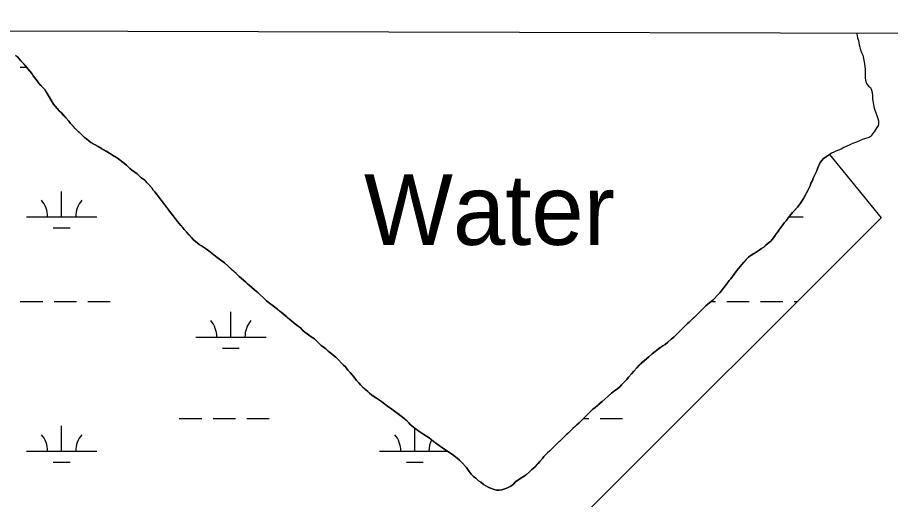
# Model space of a CAD drawing. Extents: x 3177185 to 3215018, y 812988 to 838321.
# Drawn here: x 3189655 to 3190895, y 835902 to 836586 of the extents above; entities that cross this region are included whole.
import ezdxf

# ---------------------------------------------------------------- set-up
doc = ezdxf.new("R2010")
doc.units = 0
for name, color, linetype in [('V-GRID-FRAM', 7, 'Continuous'), ('V-RIVR-IDEN', 7, 'Continuous'), ('V-TOPO-SHOR', 7, 'Continuous'), ('V-WETL-SWMP', 7, 'Continuous')]:
    doc.layers.add(name, color=color, linetype=linetype)

msp = doc.modelspace()

# ---------------------------------------------------------------- linework, layer by layer
at = {"layer": 'V-GRID-FRAM'}
msp.add_lwpolyline([(3181402.4, 836586.1), (3212801.6, 836513), (3212767.2, 818326.1), (3181352.2, 818399.3), (3181402.4, 836586.1)], dxfattribs=at)
at = {"layer": 'V-TOPO-SHOR'}
for points in [[(3190847.1, 836564.1), (3190847.1, 836564.1), (3190847.9, 836560.3), (3190848.6, 836556.5), (3190849.6, 836553.3), (3190850.9, 836547.4), (3190851.9, 836543.7), (3190852.7, 836539.9), (3190854.2, 836536.4), (3190855.8, 836532.6), (3190856.8, 836527.8), (3190857.8, 836523.3), (3190858.8, 836516.3), (3190859.3, 836512), (3190859.4, 836503.2), (3190859.1, 836499.7), (3190860.1, 836495.1), (3190861.2, 836492.2), (3190864.1, 836488.7), (3190866.7, 836486.5), (3190868.5, 836483), (3190869.3, 836479.5), (3190869.5, 836475), (3190869.7, 836469.9), (3190870.5, 836465.3), (3190871.5, 836459.2), (3190872.5, 836455.7), (3190874.6, 836450.6), (3190875.8, 836446.8), (3190877.4, 836442.8), (3190878.2, 836439.3), (3190878.4, 836435.5), (3190877.8, 836432.3), (3190875.9, 836429.7), (3190872.1, 836423.8), (3190869.9, 836420.7), (3190867.7, 836417.7), (3190865, 836415.9), (3190861.5, 836414.9), (3190856.4, 836413.1), (3190852.1, 836411.2), (3190847, 836409.2), (3190844.1, 836407.9), (3190839.5, 836406.1), (3190836.3, 836405), (3190829, 836401.4), (3190825.2, 836399.3), (3190821.2, 836397.7), (3190817.7, 836396.2), (3190814.7, 836394.9), (3190811.2, 836393.6), (3190808, 836391.2), (3190804.5, 836388.6), (3190799.6, 836385.2), (3190797.5, 836383.1), (3190795.3, 836380.1), (3190792.2, 836372.7), (3190790, 836367.6), (3190788.4, 836363.4), (3190785.6, 836357.8), (3190784.3, 836354.6)], [(3189695.3, 836480.3), (3189693.5, 836483.8), (3189690.3, 836487.3), (3189687.9, 836489.7), (3189684.5, 836493.5), (3189682.7, 836495.9), (3189680.8, 836498.6), (3189677.1, 836503.2), (3189675, 836506.5), (3189672.1, 836510), (3189669.2, 836513.8), (3189666.3, 836517.6), (3189664.2, 836519.7), (3189659.7, 836524.3), (3189657.4, 836527), (3189654.7, 836530)], [(3190060.4, 836141.8), (3190056.7, 836145.3), (3190054.3, 836147.2), (3190051.9, 836149.1), (3190047.7, 836152.1), (3190044, 836155.4), (3190041.3, 836157.6), (3190036.8, 836161.4), (3190034.5, 836163.3), (3190029.4, 836167.6), (3190026.8, 836169.8), (3190024.1, 836172), (3190018, 836176.6), (3190012.7, 836180.7), (3190008.8, 836183.9), (3190004.3, 836188), (3189999.3, 836192.9), (3189996.1, 836195.6), (3189991.6, 836199.6), (3189984.2, 836206.2), (3189981.5, 836208.1), (3189979.4, 836210.2), (3189976, 836213.2), (3189969.9, 836218.1), (3189965.4, 836222.5), (3189962.2, 836225.4), (3189959, 836228.4), (3189953.5, 836233.6), (3189948.7, 836237.6), (3189945, 836240.6), (3189938.7, 836245.5), (3189936, 836247.2), (3189932.3, 836250.2), (3189926.5, 836254.8), (3189921.7, 836258), (3189916.4, 836261.9), (3189913, 836264), (3189907.9, 836267.9), (3189905, 836270.6), (3189901.8, 836273.8), (3189898.4, 836277.6), (3189894.7, 836281.7), (3189891.8, 836284.9), (3189889.2, 836288.2), (3189887.1, 836290.6), (3189884.7, 836293.6), (3189882.3, 836296.3), (3189879.2, 836300.3), (3189874.2, 836306.8), (3189871, 836311.1), (3189865.8, 836317.9), (3189862.1, 836322.5), (3189858.9, 836326.5), (3189856, 836330.6), (3189853.1, 836334.4), (3189849.7, 836338.7), (3189847.6, 836341.1), (3189845.5, 836344.1), (3189839.2, 836351.1), (3189835.7, 836354.9), (3189833.1, 836356.8), (3189830.2, 836359), (3189827.8, 836361.2), (3189824.9, 836364.1), (3189821.7, 836366.6), (3189816.9, 836369.6), (3189814.6, 836371.5), (3189812.2, 836373.9), (3189809.5, 836376.6), (3189806.9, 836378.8), (3189801.3, 836382.9), (3189798.7, 836384.8), (3189795.5, 836387.2), (3189789.7, 836390.8), (3189785.7, 836393.5), (3189780.6, 836396.3), (3189774.3, 836400.1), (3189769.2, 836403.1), (3189765, 836405.3), (3189759.1, 836408.6), (3189756.5, 836410.7), (3189752.8, 836413.7), (3189749.8, 836415.9), (3189745.1, 836420.3), (3189740.9, 836424.3), (3189736.6, 836428.4), (3189734.3, 836431.1), (3189730.3, 836435.7), (3189727.9, 836438.9), (3189724, 836443), (3189720.8, 836446.5), (3189717.1, 836450.6), (3189714.2, 836453.5), (3189711.8, 836456.5), (3189708.1, 836460.3), (3189705.8, 836463), (3189695.3, 836480.3)], [(3190784.3, 836354.6), (3190782.1, 836350.9), (3190780.9, 836346.9), (3190779, 836343.2), (3190777.7, 836340.2), (3190775.5, 836336.3), (3190771.6, 836329.1), (3190767.5, 836322.4), (3190765.6, 836320.1), (3190763.2, 836316.9), (3190759.1, 836312.4), (3190755.9, 836309), (3190754, 836306.6), (3190751.8, 836303.9), (3190749.6, 836301), (3190746.9, 836297.6), (3190744.2, 836294.4), (3190742.5, 836291.7), (3190739.5, 836288), (3190737.6, 836285.4), (3190735.2, 836281.9), (3190732.7, 836279), (3190730.6, 836275.3), (3190727.3, 836270.8), (3190725.1, 836268.7), (3190721.6, 836265.5), (3190717.6, 836262.4), (3190715.4, 836260), (3190712.1, 836258.2), (3190708.6, 836255.8), (3190703, 836252.1), (3190700.3, 836250.5), (3190696, 836247.9), (3190693.3, 836245.8), (3190690.3, 836242.7), (3190686.8, 836238.9), (3190683.8, 836235.2), (3190681.6, 836232.3), (3190677, 836226.8), (3190672.9, 836221.5), (3190668.5, 836215.1), (3190666.1, 836212.5), (3190661.2, 836205.8), (3190659, 836203.2), (3190652.8, 836195.2), (3190649.2, 836191.5), (3190645.4, 836187.3), (3190642.7, 836184.9), (3190636, 836179.7), (3190632.7, 836176.8), (3190629.8, 836173.9), (3190624.3, 836168.3), (3190621.9, 836165.9), (3190619.5, 836163.3), (3190614, 836158), (3190609.4, 836153.5), (3190607, 836151.7), (3190603.5, 836148.3), (3190598.9, 836143.8), (3190595.1, 836139.8), (3190592.9, 836137.7), (3190590.7, 836135.3), (3190587.5, 836132.4), (3190583.7, 836129.5), (3190579.1, 836125), (3190575.1, 836121.9), (3190571.6, 836120), (3190568.9, 836117.9), (3190565.6, 836115.6), (3190560.8, 836111.9), (3190556.4, 836108.7), (3190551.8, 836104.2), (3190545.6, 836099), (3190541.6, 836095.6), (3190538.3, 836092.6), (3190535, 836088.7), (3190530.4, 836083.9), (3190527.2, 836080), (3190522.8, 836075.5), (3190520.4, 836072.3), (3190516.3, 836067.8), (3190513.1, 836064.3), (3190510.9, 836061.7), (3190507.9, 836059.3), (3190503.1, 836055.9), (3190499, 836052.5), (3190493.9, 836048.5), (3190485.5, 836040.9), (3190481.4, 836037.5), (3190479, 836035.4), (3190475.8, 836032.5), (3190472.5, 836030.1), (3190468.2, 836025.9), (3190465.5, 836023.2), (3190462.2, 836020.1), (3190459.5, 836017.1), (3190456, 836013.7), (3190453, 836010.8), (3190449.8, 836007.9), (3190447.3, 836005.5), (3190444.1, 836002.4)], [(3190444.1, 836002.4), (3190441.1, 835999.7), (3190437.8, 835996.6), (3190435.4, 835994.5), (3190431.4, 835990.8), (3190427.6, 835987.1), (3190423.5, 835983.1), (3190420, 835979.7), (3190416.5, 835976.2), (3190414.3, 835974.1), (3190410.5, 835970.4), (3190408.1, 835968.1), (3190402.9, 835963), (3190400.7, 835960.1), (3190397.2, 835955.9), (3190394.5, 835953), (3190390.2, 835948.2), (3190385.6, 835944.3), (3190382.3, 835940.8), (3190377.4, 835936.6), (3190374.7, 835934.8), (3190369.9, 835932.2), (3190365.6, 835929), (3190362.6, 835926.9), (3190359.6, 835923.7), (3190355.8, 835920.8), (3190352.1, 835918.7), (3190348.8, 835917.2), (3190343.2, 835915.4), (3190339.2, 835914.9), (3190335.4, 835914.9), (3190332.2, 835915.8), (3190326.9, 835918), (3190323.7, 835919.1), (3190320.3, 835921), (3190316.8, 835923.2), (3190313.1, 835926.2), (3190309.9, 835928.1), (3190306.2, 835931.9), (3190302.5, 835934.6), (3190299.3, 835937.9), (3190296.7, 835941.4), (3190292.8, 835947), (3190285.9, 835954.9), (3190283, 835957.6), (3190279.6, 835960.6), (3190275.1, 835963.6), (3190271.6, 835966.6), (3190267.4, 835969.3), (3190263.4, 835971.8), (3190254.4, 835978), (3190250.4, 835980.8), (3190247.8, 835982.9), (3190243.5, 835986.2), (3190239.8, 835989.2), (3190232.1, 835993.8), (3190226.3, 835997.9), (3190223.6, 835999.8), (3190219.9, 836002.5), (3190212.8, 836008.3), (3190210.7, 836010.7), (3190208.3, 836012.9), (3190204.6, 836016.1), (3190201.9, 836018.8), (3190195.3, 836023.7), (3190192.4, 836025.9), (3190186.6, 836030), (3190180.7, 836034.3), (3190174.4, 836039.2), (3190172, 836041.1), (3190169.3, 836043), (3190165.1, 836045.5), (3190158.5, 836050.1), (3190154.8, 836052.9), (3190152.6, 836055), (3190147.6, 836059.4), (3190145.2, 836061.5), (3190142.3, 836064.5), (3190140, 836067.2), (3190136.3, 836070.7), (3190132.6, 836076.1), (3190130.5, 836078.6), (3190127.6, 836082.1), (3190124.4, 836085.3), (3190120.7, 836089.9), (3190118.1, 836092.6), (3190115.2, 836095.4), (3190111, 836100), (3190107.3, 836103.8), (3190103.5, 836106.7), (3190100.1, 836109.7), (3190096.4, 836112.5), (3190092.7, 836115.7), (3190089.3, 836118.4), (3190086.3, 836120.6), (3190079.2, 836127.4), (3190076.6, 836129.8), (3190072, 836132.8), (3190066.5, 836136.9), (3190063.3, 836139.4), (3190060.4, 836141.8)]]:
    msp.add_lwpolyline(points, dxfattribs=at)
at = {"layer": 'V-WETL-SWMP'}
for p, q in [((3189652.1, 836532.4), (3189654.7, 836530)), ((3189654.7, 836530), (3189659.7, 836524.3)), ((3189658.7, 836515.6), (3189667.8, 836515.6)), ((3189659.7, 836524.3), (3189666.3, 836517.6)), ((3189666.3, 836517.6), (3189672.1, 836510)), ((3189672.1, 836510), (3189675, 836506.5)), ((3189675, 836506.5), (3189677.1, 836503.2)), ((3189677.1, 836503.2), (3189680.8, 836498.6)), ((3189680.8, 836498.6), (3189682.7, 836495.9)), ((3189682.7, 836495.9), (3189684.5, 836493.5)), ((3189684.5, 836493.5), (3189693.5, 836483.8)), ((3189693.5, 836483.8), (3189695.3, 836480.3)), ((3189695.3, 836480.3), (3189705.8, 836463)), ((3189705.8, 836463), (3189708.1, 836460.3)), ((3189708.1, 836460.3), (3189711.8, 836456.5)), ((3189711.8, 836456.5), (3189714.2, 836453.5)), ((3189714.2, 836453.5), (3189717.1, 836450.6)), ((3189717.1, 836450.6), (3189724, 836443)), ((3189724, 836443), (3189727.9, 836438.9)), ((3189727.9, 836438.9), (3189730.3, 836435.7)), ((3189730.3, 836435.7), (3189736.6, 836428.4)), ((3189736.6, 836428.4), (3189745.1, 836420.3)), ((3189745.1, 836420.3), (3189749.8, 836415.9)), ((3189749.8, 836415.9), (3189752.8, 836413.7)), ((3189752.8, 836413.7), (3189759.1, 836408.6)), ((3189759.1, 836408.6), (3189765, 836405.3)), ((3189765, 836405.3), (3189769.2, 836403.1)), ((3189769.2, 836403.1), (3189780.6, 836396.3)), ((3189780.6, 836396.3), (3189785.7, 836393.5)), ((3189785.7, 836393.5), (3189789.7, 836390.8)), ((3189789.7, 836390.8), (3189795.5, 836387.2)), ((3190799.6, 836385.2), (3190804.5, 836388.6)), ((3190804.5, 836388.6), (3190808.5, 836391.6)), ((3190808.5, 836391.6), (3190882, 836301.5)), ((3189795.5, 836387.2), (3189798.7, 836384.8)), ((3189798.7, 836384.8), (3189806.9, 836378.8)), ((3189806.9, 836378.8), (3189809.5, 836376.6)), ((3189809.5, 836376.6), (3189814.6, 836371.5)), ((3190792.2, 836372.7), (3190795.3, 836380.1)), ((3190795.3, 836380.1), (3190797.5, 836383.1)), ((3190797.5, 836383.1), (3190799.6, 836385.2)), ((3189814.6, 836371.5), (3189816.9, 836369.6)), ((3189816.9, 836369.6), (3189821.7, 836366.6)), ((3189821.7, 836366.6), (3189824.9, 836364.1)), ((3189824.9, 836364.1), (3189827.8, 836361.2)), ((3190788.4, 836363.4), (3190790, 836367.6)), ((3190790, 836367.6), (3190792.2, 836372.7)), ((3189827.8, 836361.2), (3189830.2, 836359)), ((3189830.2, 836359), (3189835.7, 836354.9)), ((3189835.7, 836354.9), (3189845.5, 836344.1)), ((3190782.1, 836350.9), (3190784.3, 836354.6)), ((3190784.3, 836354.6), (3190785.6, 836357.8)), ((3190785.6, 836357.8), (3190788.4, 836363.4)), ((3189717.5, 836303), (3189717.5, 836339)), ((3189845.5, 836344.1), (3189847.6, 836341.1)), ((3189847.6, 836341.1), (3189849.7, 836338.7)), ((3190771.6, 836329.1), (3190777.7, 836340.2)), ((3190777.7, 836340.2), (3190779, 836343.2)), ((3190779, 836343.2), (3190780.9, 836346.9)), ((3190780.9, 836346.9), (3190782.1, 836350.9)), ((3189849.7, 836338.7), (3189853.1, 836334.4)), ((3189853.1, 836334.4), (3189856, 836330.6)), ((3189856, 836330.6), (3189858.9, 836326.5)), ((3189858.9, 836326.5), (3189871, 836311.1)), ((3190767.5, 836322.4), (3190771.6, 836329.1)), ((3190755.9, 836309), (3190763.2, 836316.9)), ((3190763.2, 836316.9), (3190767.5, 836322.4)), ((3189667.5, 836303), (3189767.5, 836303)), ((3189871, 836311.1), (3189874.2, 836306.8)), ((3189874.2, 836306.8), (3189882.3, 836296.3)), ((3190882, 836301.5), (3190197.3, 835618.5)), ((3190746.9, 836297.6), (3190751.8, 836303.9)), ((3190751.1, 836303), (3190771.3, 836303)), ((3190751.8, 836303.9), (3190755.9, 836309)), ((3189882.3, 836296.3), (3189884.7, 836293.6)), ((3189884.7, 836293.6), (3189891.8, 836284.9)), ((3190739.5, 836288), (3190742.5, 836291.7)), ((3190742.5, 836291.7), (3190744.2, 836294.4)), ((3190744.2, 836294.4), (3190746.9, 836297.6)), ((3189705.5, 836287.6), (3189729.5, 836287.6)), ((3189891.8, 836284.9), (3189894.7, 836281.7)), ((3189894.7, 836281.7), (3189901.8, 836273.8)), ((3190730.6, 836275.3), (3190732.7, 836279)), ((3190732.7, 836279), (3190735.2, 836281.9)), ((3190735.2, 836281.9), (3190739.5, 836288)), ((3189901.8, 836273.8), (3189905, 836270.6)), ((3189905, 836270.6), (3189907.9, 836267.9)), ((3189907.9, 836267.9), (3189913, 836264)), ((3190717.5, 836262.4), (3190721.6, 836265.5)), ((3190721.6, 836265.5), (3190725.1, 836268.7)), ((3190725.1, 836268.7), (3190727.3, 836270.8)), ((3190727.3, 836270.8), (3190730.6, 836275.3)), ((3189913, 836264), (3189916.4, 836261.9)), ((3189916.4, 836261.9), (3189921.7, 836258)), ((3189921.7, 836258), (3189926.5, 836254.8)), ((3189926.5, 836254.8), (3189936, 836247.2)), ((3190696, 836247.9), (3190703, 836252.1)), ((3190703, 836252.1), (3190712.1, 836258.2)), ((3190712.1, 836258.2), (3190715.4, 836260)), ((3190715.4, 836260), (3190717.5, 836262.4)), ((3189936, 836247.2), (3189938.7, 836245.5)), ((3189938.7, 836245.5), (3189945, 836240.6)), ((3189945, 836240.6), (3189948.7, 836237.6)), ((3190686.8, 836238.9), (3190693.3, 836245.8)), ((3190693.3, 836245.8), (3190696, 836247.9)), ((3189948.7, 836237.6), (3189953.5, 836233.6)), ((3189953.5, 836233.6), (3189965.4, 836222.5)), ((3190677, 836226.8), (3190681.6, 836232.3)), ((3190681.6, 836232.3), (3190683.8, 836235.2)), ((3190683.8, 836235.2), (3190686.8, 836238.9)), ((3189965.4, 836222.5), (3189969.9, 836218.1)), ((3189969.9, 836218.1), (3189976, 836213.2)), ((3190666.1, 836212.5), (3190668.5, 836215.1)), ((3190668.5, 836215.1), (3190672.9, 836221.5)), ((3190672.9, 836221.5), (3190677, 836226.8)), ((3189976, 836213.2), (3189979.4, 836210.2)), ((3189979.4, 836210.2), (3189981.5, 836208.1)), ((3189981.5, 836208.1), (3189984.2, 836206.2)), ((3189984.2, 836206.2), (3189991.6, 836199.6)), ((3190652.8, 836195.2), (3190661.2, 836205.8)), ((3190661.2, 836205.8), (3190666.1, 836212.5)), ((3189991.6, 836199.6), (3189996.1, 836195.6)), ((3189996.1, 836195.6), (3189999.3, 836192.9)), ((3189999.3, 836192.9), (3190004.3, 836188)), ((3190645.4, 836187.3), (3190649.2, 836191.5)), ((3190649.2, 836191.5), (3190652.8, 836195.2)), ((3189658.7, 836182.9), (3189690.7, 836182.9)), ((3189706.7, 836182.9), (3189738.7, 836182.9)), ((3189754.7, 836182.9), (3189786.7, 836182.9)), ((3190004.3, 836188), (3190008.8, 836183.9)), ((3190008.8, 836183.9), (3190012.7, 836180.7)), ((3190012.7, 836180.7), (3190024.1, 836172)), ((3190632.7, 836176.8), (3190636, 836179.7)), ((3190636, 836179.7), (3190642.7, 836184.9)), ((3190640.1, 836182.9), (3190646.5, 836182.9)), ((3190642.7, 836184.9), (3190645.4, 836187.3)), ((3190662.5, 836182.9), (3190694.5, 836182.9)), ((3190710.5, 836182.9), (3190742.5, 836182.9)), ((3190758.5, 836182.9), (3190763.1, 836182.9)), ((3189958, 836132.2), (3189958, 836168.2)), ((3190024.1, 836172), (3190044, 836155.4)), ((3190619.5, 836163.3), (3190621.9, 836165.9)), ((3190621.9, 836165.9), (3190632.7, 836176.8)), ((3190044, 836155.4), (3190047.7, 836152.1)), ((3190607, 836151.7), (3190609.4, 836153.5)), ((3190609.4, 836153.5), (3190619.5, 836163.3)), ((3190047.7, 836152.1), (3190051.9, 836149.1)), ((3190051.9, 836149.1), (3190056.7, 836145.3)), ((3190056.7, 836145.3), (3190060.4, 836141.8)), ((3190060.4, 836141.8), (3190063.3, 836139.4)), ((3190595.1, 836139.8), (3190598.9, 836143.8)), ((3190598.9, 836143.8), (3190607, 836151.7)), ((3189908, 836132.2), (3190008, 836132.2)), ((3190063.3, 836139.4), (3190072, 836132.8)), ((3190072, 836132.8), (3190076.6, 836129.8)), ((3190076.6, 836129.8), (3190086.3, 836120.6)), ((3190579.1, 836125), (3190583.7, 836129.5)), ((3190583.7, 836129.5), (3190587.5, 836132.4)), ((3190587.5, 836132.4), (3190590.7, 836135.3)), ((3190590.7, 836135.3), (3190592.9, 836137.7)), ((3190592.9, 836137.7), (3190595.1, 836139.8)), ((3189946, 836116.8), (3189970, 836116.8)), ((3190086.3, 836120.6), (3190092.7, 836115.7)), ((3190092.7, 836115.7), (3190096.4, 836112.4)), ((3190556.4, 836108.7), (3190568.9, 836117.9)), ((3190568.9, 836117.9), (3190571.6, 836120)), ((3190571.6, 836120), (3190575.1, 836121.9)), ((3190575.1, 836121.9), (3190579.1, 836125)), ((3190096.4, 836112.4), (3190100.1, 836109.7)), ((3190100.1, 836109.7), (3190103.5, 836106.7)), ((3190103.5, 836106.7), (3190107.3, 836103.8)), ((3190107.3, 836103.8), (3190111, 836100)), ((3190541.6, 836095.5), (3190551.8, 836104.2)), ((3190551.8, 836104.2), (3190556.4, 836108.7)), ((3190111, 836100), (3190115.2, 836095.4)), ((3190115.2, 836095.4), (3190118.1, 836092.6)), ((3190118.1, 836092.6), (3190120.7, 836089.9)), ((3190535, 836088.7), (3190538.3, 836092.6)), ((3190538.3, 836092.6), (3190541.6, 836095.5)), ((3190120.7, 836089.9), (3190124.4, 836085.3)), ((3190124.4, 836085.3), (3190127.6, 836082.1)), ((3190127.6, 836082.1), (3190132.6, 836076.1)), ((3190522.8, 836075.5), (3190527.2, 836080)), ((3190527.2, 836080), (3190530.4, 836083.9)), ((3190530.4, 836083.9), (3190535, 836088.7)), ((3190132.6, 836076.1), (3190136.3, 836070.7)), ((3190136.3, 836070.7), (3190140, 836067.2)), ((3190140, 836067.2), (3190142.3, 836064.5)), ((3190513.1, 836064.3), (3190520.4, 836072.3)), ((3190520.4, 836072.3), (3190522.8, 836075.5)), ((3190142.3, 836064.5), (3190145.2, 836061.5)), ((3190145.2, 836061.5), (3190152.6, 836055)), ((3190152.6, 836055), (3190154.8, 836052.9)), ((3190499, 836052.5), (3190503.1, 836055.9)), ((3190503.1, 836055.9), (3190507.9, 836059.3)), ((3190507.9, 836059.3), (3190510.9, 836061.7)), ((3190510.9, 836061.7), (3190513.1, 836064.3)), ((3190154.8, 836052.9), (3190158.5, 836050.1)), ((3190158.5, 836050.1), (3190165.1, 836045.5)), ((3190165.1, 836045.5), (3190169.3, 836043)), ((3190169.3, 836043), (3190172, 836041.1)), ((3190172, 836041.1), (3190180.7, 836034.3)), ((3190485.5, 836040.9), (3190493.9, 836048.5)), ((3190493.9, 836048.5), (3190499, 836052.5)), ((3190180.7, 836034.3), (3190186.6, 836030)), ((3190186.6, 836030), (3190192.4, 836025.9)), ((3190462.2, 836020.1), (3190472.5, 836030.1)), ((3190472.5, 836030.1), (3190475.8, 836032.5)), ((3190475.8, 836032.5), (3190479, 836035.4)), ((3190479, 836035.4), (3190485.5, 836040.9)), ((3189884.6, 836016.8), (3189916.6, 836016.8)), ((3189932.6, 836016.8), (3189964.6, 836016.8)), ((3189980.6, 836016.8), (3190012.6, 836016.8)), ((3190192.4, 836025.9), (3190201.9, 836018.8)), ((3190201.9, 836018.8), (3190204.6, 836016.1)), ((3190453, 836010.8), (3190459.5, 836017.1)), ((3190459.1, 836016.8), (3190466.5, 836016.8)), ((3190459.5, 836017.1), (3190462.2, 836020.1)), ((3190482.5, 836016.8), (3190514.5, 836016.8)), ((3189717.5, 835970.3), (3189717.5, 836006.3)), ((3190204.6, 836016.1), (3190210.7, 836010.7)), ((3190210.7, 836010.7), (3190212.8, 836008.3)), ((3190212.8, 836008.3), (3190219.9, 836002.5)), ((3190444.1, 836002.4), (3190449.8, 836007.9)), ((3190449.8, 836007.9), (3190453, 836010.8)), ((3190219.4, 835970.3), (3190219.4, 836002.9)), ((3190219.9, 836002.5), (3190226.3, 835997.9)), ((3190226.3, 835997.9), (3190232.1, 835993.8)), ((3190232.1, 835993.8), (3190239.8, 835989.2)), ((3190431.4, 835990.8), (3190437.8, 835996.6)), ((3190437.8, 835996.6), (3190441.1, 835999.7)), ((3190441.1, 835999.7), (3190444.1, 836002.4)), ((3190239.8, 835989.2), (3190250.4, 835980.8)), ((3190250.4, 835980.8), (3190263.4, 835971.8)), ((3190402.9, 835963), (3190431.4, 835990.8)), ((3189667.5, 835970.3), (3189767.5, 835970.3)), ((3190169.4, 835970.3), (3190265.7, 835970.3)), ((3190263.4, 835971.8), (3190271.6, 835966.6)), ((3190271.6, 835966.6), (3190275.1, 835963.6)), ((3189705.5, 835954.9), (3189729.5, 835954.9)), ((3190207.4, 835954.9), (3190231.4, 835954.9)), ((3190275.1, 835963.6), (3190279.6, 835960.6)), ((3190279.6, 835960.6), (3190283, 835957.6)), ((3190283, 835957.6), (3190285.9, 835954.9)), ((3190285.9, 835954.9), (3190292.8, 835947)), ((3190390.2, 835948.2), (3190397.2, 835955.9)), ((3190397.2, 835955.9), (3190400.7, 835960.1)), ((3190400.7, 835960.1), (3190402.9, 835963)), ((3190292.8, 835947), (3190296.7, 835941.4)), ((3190382.3, 835940.8), (3190385.6, 835944.3)), ((3190385.6, 835944.3), (3190390.2, 835948.2)), ((3190296.7, 835941.4), (3190299.3, 835937.9)), ((3190299.3, 835937.9), (3190302.5, 835934.6)), ((3190302.5, 835934.6), (3190306.2, 835931.9)), ((3190306.2, 835931.9), (3190309.9, 835928.1)), ((3190362.6, 835926.9), (3190369.9, 835932.2)), ((3190369.9, 835932.2), (3190374.7, 835934.8)), ((3190374.7, 835934.8), (3190377.4, 835936.6)), ((3190377.4, 835936.6), (3190382.3, 835940.8)), ((3190309.9, 835928.1), (3190313.1, 835926.2)), ((3190313.1, 835926.2), (3190316.8, 835923.2)), ((3190316.8, 835923.2), (3190320.3, 835921)), ((3190320.3, 835921), (3190323.7, 835919.1)), ((3190323.7, 835919.1), (3190326.9, 835918)), ((3190326.9, 835918), (3190332.2, 835915.8)), ((3190343.2, 835915.4), (3190348.8, 835917.2)), ((3190348.8, 835917.2), (3190352.1, 835918.7)), ((3190352.1, 835918.7), (3190355.8, 835920.8)), ((3190355.8, 835920.8), (3190359.6, 835923.7)), ((3190359.6, 835923.7), (3190362.6, 835926.9)), ((3190332.2, 835915.8), (3190335.4, 835914.9)), ((3190335.4, 835914.9), (3190339.2, 835914.9)), ((3190339.2, 835914.9), (3190343.2, 835915.4))]:
    msp.add_line(p, q, dxfattribs=at)
for centre, start, end in [((3189662.3, 836303.5), 359.2282, 40.7718), ((3189772.8, 836303.5), 139.2282, 180.7718), ((3189902.7, 836132.7), 359.2282, 40.7718), ((3190013.2, 836132.7), 139.2282, 180.7718), ((3189662.3, 835970.8), 359.2282, 40.7718), ((3189772.8, 835970.8), 139.2282, 180.7718), ((3190164.2, 835970.8), 359.2282, 40.7718), ((3190274.7, 835970.8), 153.4673, 180.7718)]:
    msp.add_arc(centre, 35.2, start, end, dxfattribs=at)

# ---------------------------------------------------------------- texts
at = {"layer": 'V-RIVR-IDEN'}
msp.add_text('Water', height=100, dxfattribs=at).set_placement((3190147.2, 836263.2))

doc.saveas('drawing.dxf')
